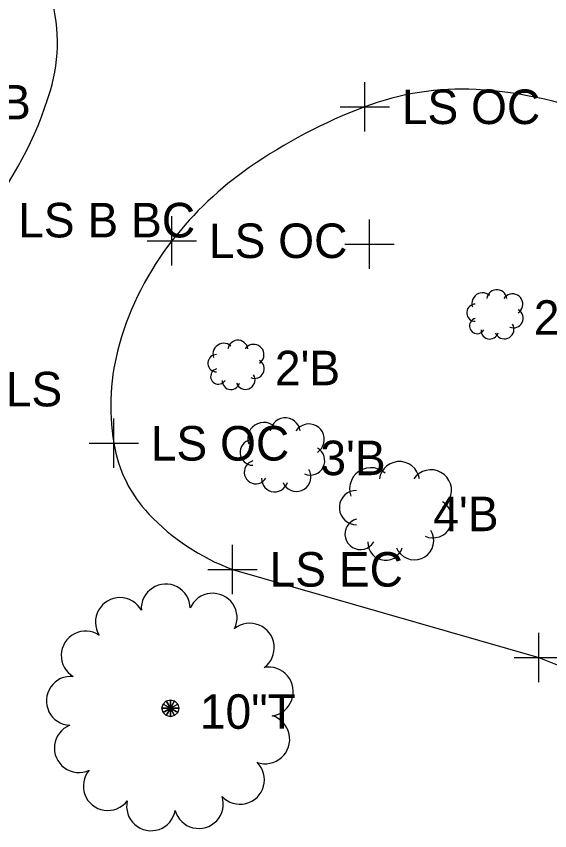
# Model space of a CAD drawing. Extents: x 1324236 to 1326110, y 459090 to 460782.
# Drawn here: x 1325429.44 to 1325451.08, y 460068.68 to 460101.69 of the extents above; entities that cross this region are included whole.
import ezdxf

# ---------------------------------------------------------------- set-up
doc = ezdxf.new("R2010")
doc.units = 0
for name, color, linetype in [('PM_X_Edge_Line', 7, 'Continuous'), ('RW_X_CL', 7, 'Continuous'), ('RW_X_Esmt_SH', 7, 'Continuous'), ('VG_X_Cells', 7, 'Continuous')]:
    doc.layers.add(name, color=color, linetype=linetype)

msp = doc.modelspace()

# ---------------------------------------------------------------- linework, layer by layer
at = {"layer": 'PM_X_Edge_Line'}
for p, q in [((1325438.216, 460079.27), (1325450.642, 460075.696)), ((1325450.642, 460075.696), (1325462.012, 460071.169))]:
    msp.add_line(p, q, dxfattribs=at)
for centre, radius, start, end in [((1325424.259, 460100.64), 6.854, 343.39, 17.6444), ((1325416.528, 460102.946), 14.922, 320.364, 343.39), ((1325447.49, 460087.664), 11.072, 86.8724, 110.6821), ((1325447.19, 460082.167), 16.578, 67.461, 86.8724), ((1325451.198, 460077.842), 21.572, 110.6821, 124.7728), ((1325447.094, 460083.752), 14.376, 124.7728, 142.0552), ((1325445.469, 460085.02), 12.315, 142.0552, 163.9714), ((1325442.474, 460085.88), 9.199, 163.9714, 189.3824), ((1325438.805, 460085.274), 5.48, 189.3824, 223.3114), ((1325441.286, 460087.613), 8.89, 223.3114, 249.7977)]:
    msp.add_arc(centre, radius, start, end, dxfattribs=at)
at = {"layer": 'RW_X_CL'}
for p, q in [((1325443.768, 460091.458), (1325443.768, 460093.458)), ((1325442.768, 460092.458), (1325444.768, 460092.458))]:
    msp.add_line(p, q, dxfattribs=at)
at = {"layer": 'RW_X_Esmt_SH'}
for p, q in [((1325443.579, 460097.023), (1325443.579, 460099.023)), ((1325442.579, 460098.023), (1325444.579, 460098.023)), ((1325435.757, 460091.592), (1325435.757, 460093.592)), ((1325434.757, 460092.592), (1325436.757, 460092.592)), ((1325433.398, 460083.381), (1325433.398, 460085.381)), ((1325432.398, 460084.38), (1325434.398, 460084.38)), ((1325438.216, 460078.27), (1325438.216, 460080.27)), ((1325437.216, 460079.27), (1325439.216, 460079.27)), ((1325450.642, 460074.696), (1325450.642, 460076.696)), ((1325449.642, 460075.696), (1325451.642, 460075.696))]:
    msp.add_line(p, q, dxfattribs=at)
at = {"layer": 'VG_X_Cells'}
for points in [[(1325449.339, 460090.255), (1325449.321, 460090.331), (1325449.289, 460090.402), (1325449.243, 460090.466), (1325449.187, 460090.519), (1325449.121, 460090.562), (1325449.049, 460090.591), (1325448.972, 460090.606), (1325448.894, 460090.606), (1325448.817, 460090.591), (1325448.745, 460090.562), (1325448.679, 460090.519), (1325448.623, 460090.466), (1325448.577, 460090.402), (1325448.545, 460090.331), (1325448.527, 460090.255)], [(1325448.643, 460090.371), (1325448.577, 460090.42), (1325448.504, 460090.456), (1325448.425, 460090.477), (1325448.344, 460090.483), (1325448.263, 460090.474), (1325448.185, 460090.449), (1325448.113, 460090.411), (1325448.05, 460090.359), (1325447.997, 460090.297), (1325447.958, 460090.226), (1325447.932, 460090.148), (1325447.921, 460090.067), (1325447.926, 460089.986), (1325447.946, 460089.907)], [(1325449.804, 460089.674), (1325449.864, 460089.723), (1325449.915, 460089.783), (1325449.953, 460089.85), (1325449.978, 460089.924), (1325449.99, 460090.001), (1325449.987, 460090.079), (1325449.969, 460090.154), (1325449.938, 460090.226), (1325449.894, 460090.29), (1325449.839, 460090.345), (1325449.775, 460090.389), (1325449.703, 460090.42), (1325449.628, 460090.438), (1325449.55, 460090.441), (1325449.473, 460090.43), (1325449.399, 460090.404), (1325449.332, 460090.366), (1325449.272, 460090.315), (1325449.223, 460090.255)], [(1325448.062, 460090.023), (1325447.998, 460090.017), (1325447.936, 460089.999), (1325447.879, 460089.971), (1325447.828, 460089.932), (1325447.784, 460089.884), (1325447.75, 460089.83), (1325447.727, 460089.77), (1325447.715, 460089.707), (1325447.715, 460089.642), (1325447.727, 460089.579), (1325447.75, 460089.519), (1325447.784, 460089.464), (1325447.828, 460089.417), (1325447.879, 460089.378), (1325447.936, 460089.35), (1325447.998, 460089.332), (1325448.062, 460089.326)], [(1325449.456, 460089.094), (1325449.526, 460089.07), (1325449.599, 460089.061), (1325449.673, 460089.065), (1325449.745, 460089.084), (1325449.812, 460089.115), (1325449.872, 460089.159), (1325449.923, 460089.213), (1325449.962, 460089.276), (1325449.989, 460089.345), (1325450.002, 460089.418), (1325450.001, 460089.492), (1325449.986, 460089.565), (1325449.957, 460089.633), (1325449.917, 460089.695), (1325449.865, 460089.748), (1325449.804, 460089.791)], [(1325448.062, 460089.442), (1325448.005, 460089.421), (1325447.952, 460089.389), (1325447.907, 460089.347), (1325447.87, 460089.298), (1325447.845, 460089.242), (1325447.83, 460089.182), (1325447.827, 460089.121), (1325447.837, 460089.06), (1325447.858, 460089.002), (1325447.89, 460088.95), (1325447.931, 460088.905), (1325447.981, 460088.868), (1325448.036, 460088.842), (1325448.096, 460088.828), (1325448.158, 460088.825), (1325448.218, 460088.834), (1325448.276, 460088.855), (1325448.329, 460088.887), (1325448.374, 460088.928), (1325448.411, 460088.978)], [(1325448.294, 460088.978), (1325448.298, 460088.909), (1325448.315, 460088.843), (1325448.344, 460088.781), (1325448.385, 460088.726), (1325448.435, 460088.679), (1325448.494, 460088.644), (1325448.558, 460088.619), (1325448.626, 460088.608), (1325448.694, 460088.61), (1325448.761, 460088.625), (1325448.824, 460088.653), (1325448.88, 460088.692), (1325448.928, 460088.741), (1325448.965, 460088.798), (1325448.991, 460088.862)], [(1325448.875, 460088.862), (1325448.91, 460088.794), (1325448.957, 460088.735), (1325449.015, 460088.686), (1325449.081, 460088.649), (1325449.154, 460088.625), (1325449.229, 460088.616), (1325449.305, 460088.622), (1325449.378, 460088.642), (1325449.446, 460088.676), (1325449.506, 460088.722), (1325449.556, 460088.78), (1325449.594, 460088.845), (1325449.618, 460088.917), (1325449.628, 460088.992), (1325449.624, 460089.068), (1325449.605, 460089.142), (1325449.572, 460089.21)], [(1325438.143, 460088.324), (1325438.078, 460088.373), (1325438.005, 460088.408), (1325437.926, 460088.43), (1325437.844, 460088.436), (1325437.763, 460088.427), (1325437.686, 460088.402), (1325437.614, 460088.363), (1325437.55, 460088.312), (1325437.498, 460088.25), (1325437.458, 460088.178), (1325437.432, 460088.101), (1325437.422, 460088.02), (1325437.427, 460087.938), (1325437.447, 460087.859)], [(1325438.84, 460088.208), (1325438.822, 460088.284), (1325438.789, 460088.355), (1325438.744, 460088.418), (1325438.687, 460088.472), (1325438.622, 460088.514), (1325438.549, 460088.543), (1325438.473, 460088.558), (1325438.395, 460088.558), (1325438.318, 460088.543), (1325438.245, 460088.514), (1325438.18, 460088.472), (1325438.123, 460088.418), (1325438.078, 460088.355), (1325438.046, 460088.284), (1325438.027, 460088.208)], [(1325439.304, 460087.627), (1325439.365, 460087.676), (1325439.415, 460087.735), (1325439.454, 460087.803), (1325439.479, 460087.877), (1325439.49, 460087.954), (1325439.487, 460088.031), (1325439.47, 460088.107), (1325439.438, 460088.178), (1325439.394, 460088.243), (1325439.339, 460088.298), (1325439.275, 460088.342), (1325439.204, 460088.373), (1325439.128, 460088.39), (1325439.05, 460088.393), (1325438.973, 460088.382), (1325438.9, 460088.357), (1325438.832, 460088.318), (1325438.773, 460088.268), (1325438.724, 460088.208)], [(1325437.563, 460087.975), (1325437.499, 460087.969), (1325437.437, 460087.952), (1325437.379, 460087.923), (1325437.328, 460087.885), (1325437.285, 460087.837), (1325437.251, 460087.782), (1325437.228, 460087.722), (1325437.216, 460087.659), (1325437.216, 460087.595), (1325437.228, 460087.532), (1325437.251, 460087.472), (1325437.285, 460087.417), (1325437.328, 460087.37), (1325437.379, 460087.331), (1325437.437, 460087.302), (1325437.499, 460087.285), (1325437.563, 460087.279)], [(1325438.956, 460087.047), (1325439.026, 460087.023), (1325439.1, 460087.014), (1325439.174, 460087.018), (1325439.246, 460087.036), (1325439.313, 460087.068), (1325439.373, 460087.112), (1325439.423, 460087.166), (1325439.462, 460087.229), (1325439.489, 460087.298), (1325439.502, 460087.371), (1325439.501, 460087.445), (1325439.486, 460087.518), (1325439.458, 460087.586), (1325439.417, 460087.648), (1325439.365, 460087.701), (1325439.304, 460087.743)], [(1325437.563, 460087.395), (1325437.505, 460087.374), (1325437.453, 460087.342), (1325437.407, 460087.3), (1325437.371, 460087.251), (1325437.345, 460087.195), (1325437.331, 460087.135), (1325437.328, 460087.074), (1325437.337, 460087.013), (1325437.358, 460086.955), (1325437.39, 460086.903), (1325437.432, 460086.857), (1325437.481, 460086.821), (1325437.537, 460086.795), (1325437.597, 460086.78), (1325437.658, 460086.778), (1325437.719, 460086.787), (1325437.777, 460086.808), (1325437.829, 460086.84), (1325437.875, 460086.881), (1325437.911, 460086.93)], [(1325438.376, 460086.814), (1325438.41, 460086.747), (1325438.458, 460086.688), (1325438.516, 460086.638), (1325438.582, 460086.601), (1325438.654, 460086.578), (1325438.729, 460086.569), (1325438.805, 460086.574), (1325438.878, 460086.595), (1325438.946, 460086.629), (1325439.006, 460086.675), (1325439.056, 460086.732), (1325439.094, 460086.798), (1325439.119, 460086.87), (1325439.129, 460086.945), (1325439.124, 460087.021), (1325439.105, 460087.094), (1325439.072, 460087.163)], [(1325437.795, 460086.93), (1325437.799, 460086.862), (1325437.816, 460086.796), (1325437.845, 460086.734), (1325437.886, 460086.678), (1325437.936, 460086.632), (1325437.994, 460086.596), (1325438.059, 460086.572), (1325438.126, 460086.561), (1325438.195, 460086.563), (1325438.261, 460086.578), (1325438.324, 460086.605), (1325438.381, 460086.644), (1325438.428, 460086.694), (1325438.466, 460086.751), (1325438.492, 460086.814)], [(1325440.96, 460084.885), (1325440.933, 460084.999), (1325440.884, 460085.105), (1325440.816, 460085.201), (1325440.732, 460085.282), (1325440.633, 460085.345), (1325440.524, 460085.388), (1325440.409, 460085.411), (1325440.292, 460085.411), (1325440.177, 460085.388), (1325440.069, 460085.345), (1325439.97, 460085.282), (1325439.885, 460085.201), (1325439.817, 460085.105), (1325439.769, 460084.999), (1325439.741, 460084.885)], [(1325439.915, 460085.059), (1325439.818, 460085.132), (1325439.708, 460085.186), (1325439.589, 460085.218), (1325439.467, 460085.227), (1325439.346, 460085.213), (1325439.229, 460085.177), (1325439.121, 460085.119), (1325439.026, 460085.041), (1325438.947, 460084.948), (1325438.888, 460084.841), (1325438.849, 460084.725), (1325438.833, 460084.603), (1325438.84, 460084.481), (1325438.871, 460084.362)], [(1325441.657, 460084.014), (1325441.748, 460084.087), (1325441.823, 460084.176), (1325441.881, 460084.278), (1325441.919, 460084.388), (1325441.936, 460084.504), (1325441.931, 460084.62), (1325441.905, 460084.734), (1325441.858, 460084.841), (1325441.792, 460084.937), (1325441.71, 460085.02), (1325441.613, 460085.086), (1325441.506, 460085.133), (1325441.393, 460085.159), (1325441.276, 460085.164), (1325441.161, 460085.147), (1325441.05, 460085.109), (1325440.949, 460085.051), (1325440.86, 460084.975), (1325440.786, 460084.885)], [(1325439.045, 460084.536), (1325438.949, 460084.528), (1325438.856, 460084.501), (1325438.77, 460084.458), (1325438.693, 460084.4), (1325438.628, 460084.329), (1325438.577, 460084.247), (1325438.542, 460084.157), (1325438.524, 460084.062), (1325438.524, 460083.966), (1325438.542, 460083.871), (1325438.577, 460083.781), (1325438.628, 460083.699), (1325438.693, 460083.628), (1325438.77, 460083.57), (1325438.856, 460083.527), (1325438.949, 460083.5), (1325439.045, 460083.492)], [(1325441.135, 460083.143), (1325441.24, 460083.108), (1325441.35, 460083.094), (1325441.461, 460083.1), (1325441.569, 460083.128), (1325441.67, 460083.175), (1325441.759, 460083.241), (1325441.835, 460083.322), (1325441.894, 460083.417), (1325441.934, 460083.52), (1325441.954, 460083.63), (1325441.952, 460083.741), (1325441.93, 460083.85), (1325441.887, 460083.953), (1325441.826, 460084.045), (1325441.748, 460084.125), (1325441.657, 460084.188)], [(1325439.045, 460083.666), (1325438.958, 460083.634), (1325438.879, 460083.586), (1325438.811, 460083.524), (1325438.757, 460083.449), (1325438.718, 460083.366), (1325438.696, 460083.276), (1325438.692, 460083.184), (1325438.706, 460083.093), (1325438.738, 460083.006), (1325438.786, 460082.927), (1325438.848, 460082.859), (1325438.922, 460082.805), (1325439.006, 460082.766), (1325439.096, 460082.744), (1325439.188, 460082.74), (1325439.279, 460082.754), (1325439.365, 460082.785), (1325439.444, 460082.833), (1325439.513, 460082.895), (1325439.567, 460082.969)], [(1325444.404, 460083.168), (1325444.273, 460083.266), (1325444.127, 460083.337), (1325443.969, 460083.38), (1325443.806, 460083.392), (1325443.644, 460083.373), (1325443.489, 460083.325), (1325443.345, 460083.247), (1325443.218, 460083.144), (1325443.113, 460083.019), (1325443.034, 460082.877), (1325442.982, 460082.722), (1325442.961, 460082.56), (1325442.971, 460082.397), (1325443.011, 460082.239)], [(1325445.797, 460082.936), (1325445.761, 460083.087), (1325445.696, 460083.229), (1325445.605, 460083.357), (1325445.492, 460083.465), (1325445.361, 460083.549), (1325445.216, 460083.607), (1325445.063, 460083.637), (1325444.906, 460083.637), (1325444.753, 460083.607), (1325444.608, 460083.549), (1325444.477, 460083.465), (1325444.364, 460083.357), (1325444.273, 460083.229), (1325444.208, 460083.087), (1325444.172, 460082.936)], [(1325440.264, 460082.795), (1325440.316, 460082.694), (1325440.387, 460082.605), (1325440.474, 460082.531), (1325440.573, 460082.475), (1325440.682, 460082.44), (1325440.795, 460082.427), (1325440.908, 460082.435), (1325441.018, 460082.465), (1325441.12, 460082.516), (1325441.21, 460082.586), (1325441.285, 460082.672), (1325441.342, 460082.77), (1325441.379, 460082.878), (1325441.394, 460082.991), (1325441.387, 460083.105), (1325441.358, 460083.215), (1325441.309, 460083.317)], [(1325446.726, 460081.775), (1325446.847, 460081.872), (1325446.948, 460081.991), (1325447.025, 460082.126), (1325447.075, 460082.274), (1325447.098, 460082.427), (1325447.091, 460082.583), (1325447.056, 460082.735), (1325446.994, 460082.877), (1325446.906, 460083.006), (1325446.796, 460083.116), (1325446.668, 460083.203), (1325446.525, 460083.266), (1325446.374, 460083.301), (1325446.218, 460083.307), (1325446.064, 460083.285), (1325445.917, 460083.234), (1325445.782, 460083.157), (1325445.663, 460083.056), (1325445.565, 460082.936)], [(1325439.393, 460082.969), (1325439.399, 460082.866), (1325439.424, 460082.767), (1325439.468, 460082.674), (1325439.529, 460082.591), (1325439.604, 460082.521), (1325439.692, 460082.468), (1325439.788, 460082.432), (1325439.89, 460082.415), (1325439.992, 460082.418), (1325440.093, 460082.44), (1325440.187, 460082.481), (1325440.271, 460082.54), (1325440.343, 460082.614), (1325440.399, 460082.7), (1325440.438, 460082.795)], [(1325443.243, 460082.471), (1325443.115, 460082.459), (1325442.991, 460082.424), (1325442.876, 460082.367), (1325442.774, 460082.289), (1325442.687, 460082.194), (1325442.619, 460082.085), (1325442.573, 460081.965), (1325442.549, 460081.839), (1325442.549, 460081.71), (1325442.573, 460081.584), (1325442.619, 460081.464), (1325442.687, 460081.355), (1325442.774, 460081.26), (1325442.876, 460081.182), (1325442.991, 460081.125), (1325443.115, 460081.09), (1325443.243, 460081.078)], [(1325446.029, 460080.613), (1325446.17, 460080.567), (1325446.317, 460080.547), (1325446.465, 460080.556), (1325446.609, 460080.593), (1325446.743, 460080.656), (1325446.862, 460080.744), (1325446.963, 460080.852), (1325447.042, 460080.978), (1325447.095, 460081.116), (1325447.122, 460081.262), (1325447.12, 460081.41), (1325447.09, 460081.556), (1325447.033, 460081.693), (1325446.952, 460081.816), (1325446.848, 460081.922), (1325446.726, 460082.007)], [(1325443.243, 460081.31), (1325443.127, 460081.268), (1325443.022, 460081.204), (1325442.932, 460081.121), (1325442.859, 460081.021), (1325442.808, 460080.91), (1325442.778, 460080.791), (1325442.773, 460080.668), (1325442.792, 460080.546), (1325442.834, 460080.431), (1325442.898, 460080.326), (1325442.981, 460080.235), (1325443.08, 460080.162), (1325443.191, 460080.11), (1325443.311, 460080.081), (1325443.434, 460080.075), (1325443.555, 460080.094), (1325443.671, 460080.136), (1325443.776, 460080.199), (1325443.867, 460080.282), (1325443.94, 460080.381)], [(1325444.868, 460080.149), (1325444.938, 460080.014), (1325445.033, 460079.895), (1325445.149, 460079.797), (1325445.281, 460079.723), (1325445.426, 460079.676), (1325445.576, 460079.658), (1325445.728, 460079.669), (1325445.874, 460079.71), (1325446.01, 460079.777), (1325446.13, 460079.87), (1325446.23, 460079.985), (1325446.306, 460080.116), (1325446.355, 460080.26), (1325446.375, 460080.41), (1325446.366, 460080.562), (1325446.328, 460080.709), (1325446.262, 460080.846)], [(1325443.707, 460080.381), (1325443.715, 460080.244), (1325443.749, 460080.112), (1325443.807, 460079.988), (1325443.888, 460079.877), (1325443.989, 460079.784), (1325444.106, 460079.713), (1325444.234, 460079.665), (1325444.37, 460079.642), (1325444.507, 460079.646), (1325444.64, 460079.676), (1325444.766, 460079.731), (1325444.879, 460079.809), (1325444.974, 460079.907), (1325445.049, 460080.022), (1325445.101, 460080.149)]]:
    msp.add_lwpolyline(points, dxfattribs=at)
for points in [[(1325435.398, 460073.811), (1325435.695, 460073.639), (1325435.695, 460073.639), (1325435.352, 460073.639)], [(1325435.523, 460073.937), (1325435.695, 460073.639), (1325435.695, 460073.639), (1325435.398, 460073.811)], [(1325435.695, 460073.983), (1325435.695, 460073.639), (1325435.695, 460073.639), (1325435.523, 460073.937)], [(1325435.867, 460073.937), (1325435.695, 460073.639), (1325435.695, 460073.639), (1325435.695, 460073.983)], [(1325435.992, 460073.811), (1325435.695, 460073.639), (1325435.695, 460073.639), (1325435.867, 460073.937)], [(1325436.038, 460073.639), (1325435.695, 460073.639), (1325435.695, 460073.639), (1325435.992, 460073.811)], [(1325435.352, 460073.639), (1325435.695, 460073.639), (1325435.695, 460073.639), (1325435.398, 460073.468)], [(1325435.398, 460073.468), (1325435.695, 460073.639), (1325435.695, 460073.639), (1325435.523, 460073.342)], [(1325435.523, 460073.342), (1325435.695, 460073.639), (1325435.695, 460073.639), (1325435.695, 460073.296)], [(1325435.695, 460073.296), (1325435.695, 460073.639), (1325435.695, 460073.639), (1325435.867, 460073.342)], [(1325435.867, 460073.342), (1325435.695, 460073.639), (1325435.695, 460073.639), (1325435.992, 460073.468)], [(1325435.992, 460073.468), (1325435.695, 460073.639), (1325435.695, 460073.639), (1325436.038, 460073.639)]]:
    msp.add_lwpolyline(points, close=True, dxfattribs=at)
for centre, start, end in [((1325435.506, 460077.683), 1.241, 184.1237), ((1325433.648, 460077.132), 28.9333, 211.816), ((1325437.407, 460077.308), 333.5487, 156.4314), ((1325438.916, 460076.093), 305.8564, 128.7391), ((1325432.259, 460075.781), 56.6256, 239.5083), ((1325439.687, 460074.315), 278.1641, 101.0468), ((1325431.658, 460073.939), 84.3179, 267.2006), ((1325439.543, 460072.382), 250.4718, 73.3545), ((1325431.981, 460072.028), 112.0103, 294.8929), ((1325438.519, 460070.738), 222.7795, 45.6622), ((1325433.155, 460070.487), 139.7026, 322.5852), ((1325434.911, 460069.667), 167.3949, 350.2776), ((1325436.847, 460069.758), 195.0872, 17.9699)]:
    msp.add_arc(centre, 0.992, start, end, dxfattribs=at)

# ---------------------------------------------------------------- texts
at = {"layer": 'RW_X_Esmt_SH'}
for s, p in [('LS OC', (1325445.079, 460097.323)), ('LS B BC', (1325429.519, 460092.728)), ('LS OC', (1325437.257, 460091.892)), ('LS EC CLS', (1325421.734, 460085.878)), ('LS OC', (1325434.898, 460083.681)), ('LS EC', (1325439.716, 460078.57))]:
    msp.add_text(s, height=1.4, dxfattribs=at).set_placement(p)
at = {"layer": 'VG_X_Cells'}
for s, p in [("6'B", (1325427.388, 460097.51)), ("2'B", (1325450.433, 460088.78)), ("2'B", (1325439.933, 460086.733)), ("3'B", (1325441.779, 460083.089)), ("4'B", (1325446.359, 460080.819)), ('10"T', (1325436.891, 460072.806))]:
    msp.add_text(s, height=1.4, dxfattribs=at).set_placement(p)

doc.saveas('drawing.dxf')
